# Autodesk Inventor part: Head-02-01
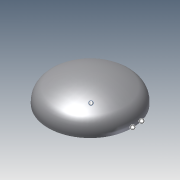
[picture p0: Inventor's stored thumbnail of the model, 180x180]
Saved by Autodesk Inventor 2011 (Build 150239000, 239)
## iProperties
Created: 2010-05
Part Number: Head-02-01
Document SubType Name: Modeling
Designer: mklassen
Density: 1 g/cm^3
Description: HEAD TORISPHERICAL 0.8 36"x 0.625"
THK: 0.625 in
OD: 36.000 in
LIP: 1.000 in
DRFAC: 0.850 ul
KRFAC: 0.154 ul
Author: mklassen
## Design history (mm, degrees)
sketch "skConical"
  geometry: L1 (0, -141.168)-(0, 847.008) reference; L2 (-135.363, 0)-(563.935, 0) reference; L3 (441.325, 0)-(441.325, 25.4); L4 (416.166, 105.729)-(20.862, 674.889); L5 (0, 685.8)-(-35.463, 685.8); L6 (33.901, 683.945)-(429.204, 114.785); L7 (457.2, 25.4)-(457.2, 0); L8 (441.325, 0)-(457.2, 0); L9 (0, 685.8)-(0, 701.675); A1 r 140.818 centre (300.507, 25.4) between (441.325, 25.4) and (416.166, 105.729); A2 r 25.4 centre (0, 660.4) between (20.862, 674.889) and (0, 685.8); A3 r 41.275 centre (0, 660.4) between (33.901, 683.945) and (0, 701.675); A4 r 156.693 centre (300.507, 25.4) between (457.2, 25.4) and (429.204, 114.785); 1 further point
  constraints: 14 end point, 8 point on circle, 4 centre point, 4 tangent, 2 perpendicular, 2 point on line, 1 collinear, 1 horizontal, 3 other
  dimensions: "d6" = 140.8176 radius of A1 (derived); "d7" = 15.875 distance between parallel lines of L7 L3 (derived); "d8" = 25.4 distance of L3.start L3.end (= LIP); "d9" = 914.4 diameter of L7 L1 (derived); "d10" = 685.8 distance between parallel lines of L5 L2 (derived); "d11" = 25.4 radius of A2
revolve "Conical" sketch "skConical" stored, may be unused: angle "d12" = 90 deg
sketch "skDiffuser"
  geometry: L1 (0, -418.496)-(0, 724.257) reference; L2 (-95.259, 0)-(571.555, 0) reference; L3 (441.325, 0)-(441.325, 142.234); L4 (441.325, 0)-(457.2, 0); L5 (0, -216.233)-(0, -232.108); A1 r 140.818 centre (300.507, 0) between (366.999, -124.131) and (441.325, 0); A2 r 777.24 centre (0, 561.007) between (0, -216.233) and (366.999, -124.131); A3 r 793.115 centre (0, 561.007) between (0, -232.108) and (374.495, -138.125); A4 r 156.693 centre (300.507, 0) between (374.495, -138.125) and (457.2, 0); 1 further point
  constraints: 8 point on circle, 6 end point, 4 centre point, 3 point on line, 2 perpendicular, 2 tangent, 1 collinear, 1 other
  dimensions: "d15" = 140.8176 radius of A1 (derived); "d16" = 777.24 radius of A2 (derived); "d17" = 15.875 distance of L3.start L4.end (derived); "d18" = 914.4 diameter of L4.end L1 (derived)
revolve "Diffuser" sketch "skDiffuser" stored, may be unused: angle "d19" = 90 deg
sketch "skEllipsoidal"
  geometry: L1 (-110.32, 0)-(595.975, 0) reference; L2 (0, -64.258)-(0, 365.786) reference; L3 (441.325, 0)-(457.2, 0); L4 (0, 212.725)-(0, 228.6); 2 further points; 1 other entity
  constraints: 4 end point, 2 point on line, 1 coincident, 1 collinear, 1 horizontal, 1 perpendicular, 7 other
  dimensions: "d22" = 914.4 diameter of L3.end L2 (derived); "d23" = 228.6 distance from line of L4.end L1 (derived); "d24" = 15.875 distance of L3.start L3.end (derived)
revolve "Ellipsoidal" sketch "skEllipsoidal" stored, may be unused: angle "d25" = 90 deg
sketch "skFlat"
  geometry: L1 (-97.93, 0)-(587.583, 0) reference; L2 (0, -42.909)-(0, 257.454) reference; L3 (457.2, 0)-(457.2, 25.4); L4 (300.507, 182.093)-(0, 182.093); L5 (0, 166.218)-(300.507, 166.218); L6 (441.325, 25.4)-(441.325, 0); L7 (0, 166.218)-(0, 182.093); L8 (441.325, 0)-(457.2, 0); A1 r 156.693 centre (300.507, 25.4) between (457.2, 25.4) and (300.507, 182.093); A2 r 140.818 centre (300.507, 25.4) between (441.325, 25.4) and (300.507, 166.218); 1 further point
  constraints: 12 end point, 4 point on circle, 2 centre point, 2 perpendicular, 2 point on line, 2 tangent, 1 collinear, 1 parallel, 2 other
  dimensions: "d28" = 914.4 diameter of L3 L2 (derived); "d31" = 140.8176 radius of A2 (derived); "d32" = 15.875 distance of L6.end L3.start (derived); "d33" = 25.4 distance of L6.start L6.end (= LIP)
revolve "Flat" sketch "skFlat" stored, may be unused: angle "d34" = 90 deg
sketch "skHemispherical"
  geometry: L1 (0, -110.378)-(0, 662.267) reference; L2 (-110.378, 0)-(662.267, 0) reference; L3 (441.325, 0)-(457.2, 0); L4 (0, 441.325)-(0, 457.2); A1 r 457.2 centre (0, 0) between (457.2, 0) and (0, 457.2); A2 r 441.325 centre (0, 0) between (441.325, 0) and (0, 441.325); 1 further point
  constraints: 5 point on circle, 4 end point, 2 centre point, 2 collinear, 2 point on line, 1 coincident
  dimensions: "d37" = 914.4 diameter of L3.end L1 (derived); "d38" = 15.875 distance of L3.start L3.end (derived)
revolve "Hemispherical" sketch "skHemispherical" stored, may be unused: angle "d39" = 90 deg
sketch "skTorispherical"
  geometry: L1 (-95.259, 0)-(571.555, 0) reference; L2 (0, -698.857)-(0, 443.896) reference; L3 (441.325, 0)-(441.325, 25.4); L4 (457.2, 25.4)-(457.2, 0); L5 (441.325, 0)-(457.2, 0); L6 (0, 241.633)-(0, 257.508); A1 r 140.818 centre (300.507, 25.4) between (441.325, 25.4) and (366.999, 149.531); A2 r 777.24 centre (0, -535.607) between (366.999, 149.531) and (0, 241.633); A3 r 793.115 centre (0, -535.607) between (374.495, 163.525) and (0, 257.508); A4 r 156.693 centre (300.507, 25.4) between (457.2, 25.4) and (374.495, 163.525); 1 further point
  constraints: 8 end point, 8 point on circle, 4 centre point, 2 perpendicular, 2 point on line, 2 tangent, 1 collinear, 1 vertical alignment, 2 other
  dimensions: "d43" = 25.4 distance of L3.start L3.end (= LIP); "d44" = 140.8176 radius of A1 (derived); "d45" = 777.24 radius of A2 (derived); "d46" = 15.875 distance of L3.start L4.end (derived); "d47" = 914.4 diameter of L4 L2 (derived)
revolve "Torispherical" sketch "skTorispherical" stored, may be unused: angle "d48" = 90 deg
body "Solid1"
other parameters: "LIP" = 25.4 [user parameter; used in 3 equation terms], "DRFAC" = 0.85 [user parameter; used in 2 equation terms], "KRFAC" = 0.154 [user parameter; used in 4 equation terms], "d13" = 0, "d14" = 0, "d20" = 0, "d21" = 0, "d26" = 0, "d27" = 0, "d35" = 0, "d36" = 0, "d40" = 0, "d41" = 0, "d49" = 0, "d50" = 0, "d51" = 0, "d52" = 0
